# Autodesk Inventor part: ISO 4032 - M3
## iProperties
Library Location: C:\Programmi\Autodesk\Inventor 6\content
Library: local
SubLibrary: ISO
Family: 51
Member: 40
Member Major Revision: 1
Member Minor Revision: 1
Comments: To add or edit properties for Autodesk Inventor files, use iProperties.
Created: 2004-02
Part Number: ISO 4032 - M3
Vendor: Autodesk Inc.
Document SubType Name: Modeling
Designer: lollo
Description: Dado esagonale
Standard: ISO 4032 M3
Alert: To add or edit properties for Autodesk Inventor files, use iProperties.
Control State: 0
Master: False
Checked Out: False
Shininess: 64.0
Length Units: 11269
Angle Units: 11279
Time Units: 11290
Mass Units: 11283
Length Display Precision: 3
Angle Display Precision: 2
Compacted: True
EGR: 1
Density: 0.0
Volumn: 0.0
Area: 0.0
PropertySet Name: Model Information
Author: lollo
Revision Number: 1
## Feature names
1. Corpo [Extrusion]
2. Smusso1 [Revolution]
3. Filettatura [Hole]
4. Smusso2 [Chamfer]
5. Smusso3 [Chamfer]
